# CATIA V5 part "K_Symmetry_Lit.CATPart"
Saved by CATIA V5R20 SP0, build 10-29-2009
Part number: Symmetry of Lit
Bounding box of the stored display mesh (mm): x 0 to 300, y -15 to 45, z 0 to 1000
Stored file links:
  G:\Khaled_CFAO_2011\SIL\SIL_GR2\zthiebault\Khaled\CAD_ThinkMOTION\K_Symmetry_Lit.CATPart
  G:\Khaled_CFAO_2011\SIL\SIL_GR2\zthiebault\Khaled\CAD_ThinkMOTION\K_Lit.CATPart
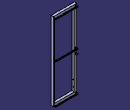
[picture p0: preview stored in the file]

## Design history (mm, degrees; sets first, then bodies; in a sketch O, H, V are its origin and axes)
Body1 (main body)
  Body2 "Corps du corps principal d'origine"
    Solid1: linked copy from another document
  Assemble1: tool Body2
